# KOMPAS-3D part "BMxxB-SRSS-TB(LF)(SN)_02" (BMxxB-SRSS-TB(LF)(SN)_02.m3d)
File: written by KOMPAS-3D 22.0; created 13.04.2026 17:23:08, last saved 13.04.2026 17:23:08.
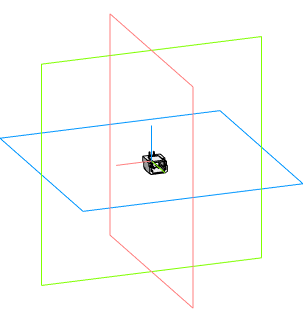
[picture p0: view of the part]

Document properties: Автор: Andrey; Полное имя файла: C:\Users\User1\Documents\BMxxB-SRSS-TB(LF)(SN)_02.m3d

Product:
- Part/product: BMxxB-SRSS-TB(LF)(SN)_02

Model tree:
1. Операция без истории:1
2. Операция без истории:2
3. Операция без истории:3
4. Операция без истории:4
5. Операция без истории:5
6. Операция без истории:6
7. Операция без истории:7
8. Операция без истории:8
9. Операция без истории:9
